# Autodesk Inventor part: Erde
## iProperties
Created: 2005-06
Part Number: Erde
Material: .
Document SubType Name: Modeling
Designer: rsc
Manufacturer: Standard
Standards Organization: Custom
Kanten: brechen
Oberflächen: Ra 3,2
Radien: 2
Toleranzen: ISO 2768 - m
Author: rsc
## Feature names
1. Drehung1 [Revolution]
2. Trennen1
